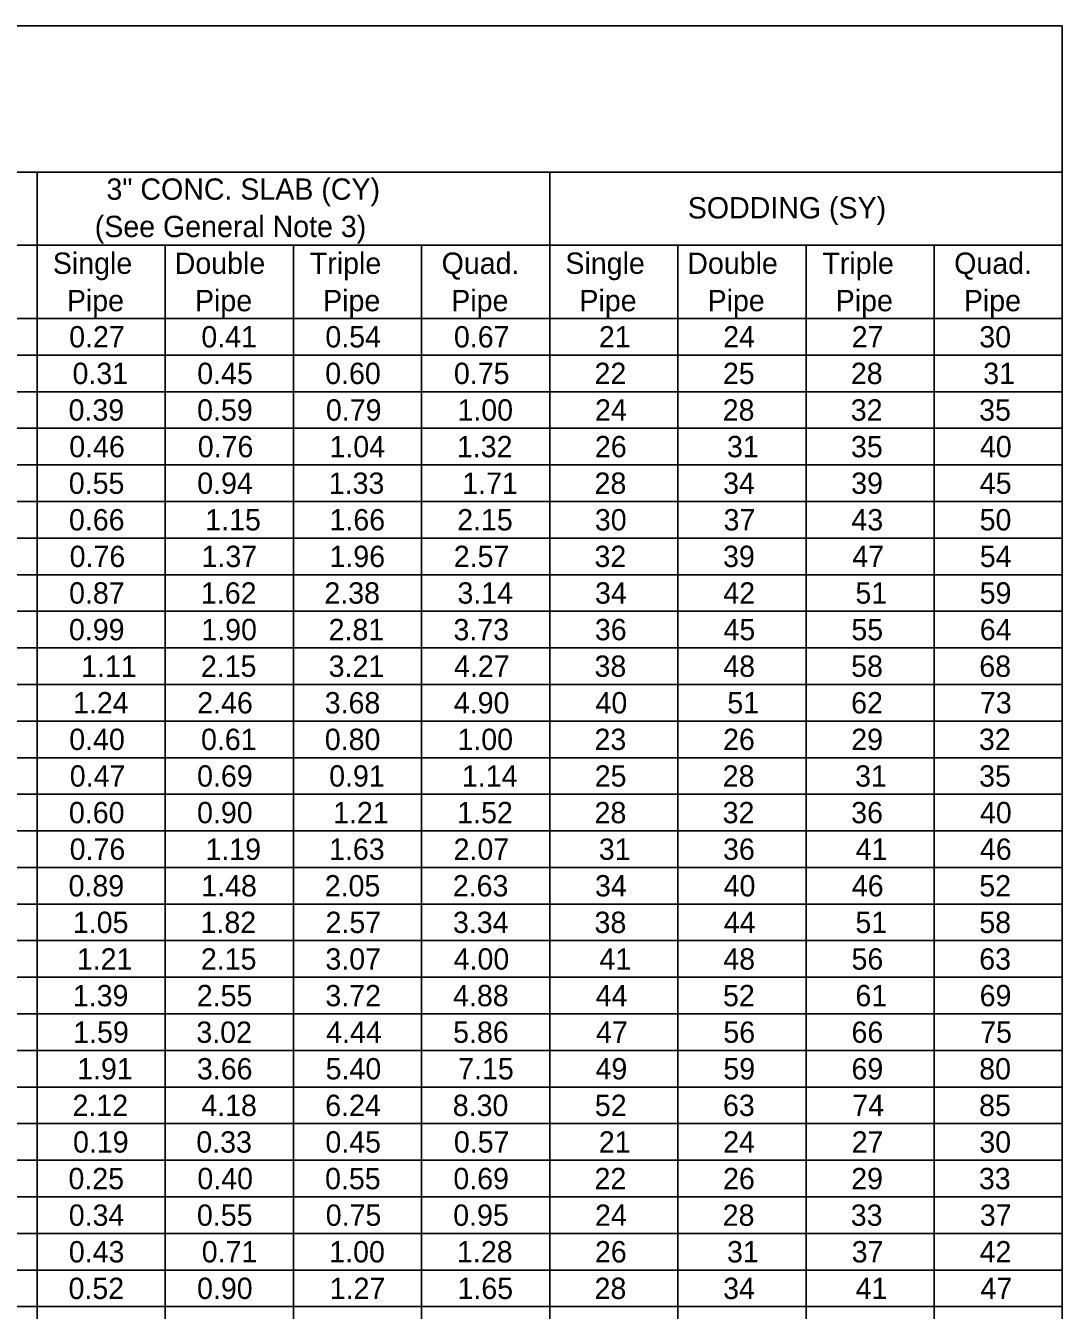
# Model space of a CAD drawing. Extents: x 1.7 to 14.6, y 0 to 8.4.
# Drawn here: x 10.062 to 13.46, y 4.218 to 8.43 of the extents above; entities that cross this region are included whole.
import ezdxf

# ---------------------------------------------------------------- set-up
doc = ezdxf.new("R2010")
doc.units = 0
doc.layers.add('Table', color=7, linetype='Continuous')

msp = doc.modelspace()

# ---------------------------------------------------------------- linework, layer by layer
at = {"layer": 'Table'}
msp.add_line((1.94, 8.43), (13.46, 8.43), dxfattribs=at)
for points in [[(13.46, 8.43), (13.46, 7.83), (13.46, 7.47), (13.46, 7.35), (13.46, 7.23), (13.46, 7.11), (13.46, 6.99), (13.46, 6.87), (13.46, 6.75), (13.46, 6.63), (13.46, 6.51), (13.46, 6.39), (13.46, 6.27), (13.46, 6.15), (13.46, 6.03), (13.46, 5.91), (13.46, 5.79), (13.46, 5.67), (13.46, 5.55), (13.46, 5.43), (13.46, 5.31), (13.46, 5.19), (13.46, 5.07), (13.46, 4.95), (13.46, 4.83), (13.46, 4.71), (13.46, 4.59), (13.46, 4.47), (13.46, 4.35), (13.46, 4.23), (13.46, 4.11)], [(13.46, 7.95), (11.78, 7.95), (10.1, 7.95), (8.42, 7.95), (8.06, 7.95), (6.38, 7.95), (6.02, 7.95), (5.66, 7.95), (5.42, 7.95), (4.94, 7.95), (4.52, 7.95), (4.04, 7.95), (3.62, 7.95), (3.2, 7.95), (2.9, 7.95), (2.6, 7.95), (2.3, 7.95), (1.94, 7.95)], [(10.1, 7.95), (10.1, 7.71), (10.1, 7.47), (10.1, 7.35), (10.1, 7.23), (10.1, 7.11), (10.1, 6.99), (10.1, 6.87), (10.1, 6.75), (10.1, 6.63), (10.1, 6.51), (10.1, 6.39), (10.1, 6.27), (10.1, 6.15), (10.1, 6.03), (10.1, 5.91), (10.1, 5.79), (10.1, 5.67), (10.1, 5.55), (10.1, 5.43), (10.1, 5.31), (10.1, 5.19), (10.1, 5.07), (10.1, 4.95), (10.1, 4.83), (10.1, 4.71), (10.1, 4.59), (10.1, 4.47), (10.1, 4.35), (10.1, 4.23), (10.1, 4.11)], [(11.78, 7.95), (11.78, 7.71), (11.78, 7.47), (11.78, 7.35), (11.78, 7.23), (11.78, 7.11), (11.78, 6.99), (11.78, 6.87), (11.78, 6.75), (11.78, 6.63), (11.78, 6.51), (11.78, 6.39), (11.78, 6.27), (11.78, 6.15), (11.78, 6.03), (11.78, 5.91), (11.78, 5.79), (11.78, 5.67), (11.78, 5.55), (11.78, 5.43), (11.78, 5.31), (11.78, 5.19), (11.78, 5.07), (11.78, 4.95), (11.78, 4.83), (11.78, 4.71), (11.78, 4.59), (11.78, 4.47), (11.78, 4.35), (11.78, 4.23), (11.78, 4.11)], [(8.42, 7.71), (8.84, 7.71), (9.26, 7.71), (9.68, 7.71), (10.1, 7.71), (10.52, 7.71), (10.94, 7.71), (11.36, 7.71), (11.78, 7.71), (12.2, 7.71), (12.62, 7.71), (13.04, 7.71), (13.46, 7.71)], [(10.52, 7.71), (10.52, 7.47), (10.52, 7.35), (10.52, 7.23), (10.52, 7.11), (10.52, 6.99), (10.52, 6.87), (10.52, 6.75), (10.52, 6.63), (10.52, 6.51), (10.52, 6.39), (10.52, 6.27), (10.52, 6.15), (10.52, 6.03), (10.52, 5.91), (10.52, 5.79), (10.52, 5.67), (10.52, 5.55), (10.52, 5.43), (10.52, 5.31), (10.52, 5.19), (10.52, 5.07), (10.52, 4.95), (10.52, 4.83), (10.52, 4.71), (10.52, 4.59), (10.52, 4.47), (10.52, 4.35), (10.52, 4.23), (10.52, 4.11)], [(10.94, 7.71), (10.94, 7.47), (10.94, 7.35), (10.94, 7.23), (10.94, 7.11), (10.94, 6.99), (10.94, 6.87), (10.94, 6.75), (10.94, 6.63), (10.94, 6.51), (10.94, 6.39), (10.94, 6.27), (10.94, 6.15), (10.94, 6.03), (10.94, 5.91), (10.94, 5.79), (10.94, 5.67), (10.94, 5.55), (10.94, 5.43), (10.94, 5.31), (10.94, 5.19), (10.94, 5.07), (10.94, 4.95), (10.94, 4.83), (10.94, 4.71), (10.94, 4.59), (10.94, 4.47), (10.94, 4.35), (10.94, 4.23), (10.94, 4.11)], [(11.36, 7.71), (11.36, 7.47), (11.36, 7.35), (11.36, 7.23), (11.36, 7.11), (11.36, 6.99), (11.36, 6.87), (11.36, 6.75), (11.36, 6.63), (11.36, 6.51), (11.36, 6.39), (11.36, 6.27), (11.36, 6.15), (11.36, 6.03), (11.36, 5.91), (11.36, 5.79), (11.36, 5.67), (11.36, 5.55), (11.36, 5.43), (11.36, 5.31), (11.36, 5.19), (11.36, 5.07), (11.36, 4.95), (11.36, 4.83), (11.36, 4.71), (11.36, 4.59), (11.36, 4.47), (11.36, 4.35), (11.36, 4.23), (11.36, 4.11)], [(12.2, 7.71), (12.2, 7.47), (12.2, 7.35), (12.2, 7.23), (12.2, 7.11), (12.2, 6.99), (12.2, 6.87), (12.2, 6.75), (12.2, 6.63), (12.2, 6.51), (12.2, 6.39), (12.2, 6.27), (12.2, 6.15), (12.2, 6.03), (12.2, 5.91), (12.2, 5.79), (12.2, 5.67), (12.2, 5.55), (12.2, 5.43), (12.2, 5.31), (12.2, 5.19), (12.2, 5.07), (12.2, 4.95), (12.2, 4.83), (12.2, 4.71), (12.2, 4.59), (12.2, 4.47), (12.2, 4.35), (12.2, 4.23), (12.2, 4.11)], [(12.62, 7.71), (12.62, 7.47), (12.62, 7.35), (12.62, 7.23), (12.62, 7.11), (12.62, 6.99), (12.62, 6.87), (12.62, 6.75), (12.62, 6.63), (12.62, 6.51), (12.62, 6.39), (12.62, 6.27), (12.62, 6.15), (12.62, 6.03), (12.62, 5.91), (12.62, 5.79), (12.62, 5.67), (12.62, 5.55), (12.62, 5.43), (12.62, 5.31), (12.62, 5.19), (12.62, 5.07), (12.62, 4.95), (12.62, 4.83), (12.62, 4.71), (12.62, 4.59), (12.62, 4.47), (12.62, 4.35), (12.62, 4.23), (12.62, 4.11)], [(13.04, 7.71), (13.04, 7.47), (13.04, 7.35), (13.04, 7.23), (13.04, 7.11), (13.04, 6.99), (13.04, 6.87), (13.04, 6.75), (13.04, 6.63), (13.04, 6.51), (13.04, 6.39), (13.04, 6.27), (13.04, 6.15), (13.04, 6.03), (13.04, 5.91), (13.04, 5.79), (13.04, 5.67), (13.04, 5.55), (13.04, 5.43), (13.04, 5.31), (13.04, 5.19), (13.04, 5.07), (13.04, 4.95), (13.04, 4.83), (13.04, 4.71), (13.04, 4.59), (13.04, 4.47), (13.04, 4.35), (13.04, 4.23), (13.04, 4.11)], [(6.02, 7.47), (6.38, 7.47), (6.8, 7.47), (7.22, 7.47), (7.64, 7.47), (8.06, 7.47), (8.42, 7.47), (8.84, 7.47), (9.26, 7.47), (9.68, 7.47), (10.1, 7.47), (10.52, 7.47), (10.94, 7.47), (11.36, 7.47), (11.78, 7.47), (12.2, 7.47), (12.62, 7.47), (13.04, 7.47), (13.46, 7.47)], [(6.02, 7.35), (6.38, 7.35), (6.8, 7.35), (7.22, 7.35), (7.64, 7.35), (8.06, 7.35), (8.42, 7.35), (8.84, 7.35), (9.26, 7.35), (9.68, 7.35), (10.1, 7.35), (10.52, 7.35), (10.94, 7.35), (11.36, 7.35), (11.78, 7.35), (12.2, 7.35), (12.62, 7.35), (13.04, 7.35), (13.46, 7.35)], [(6.02, 7.23), (6.38, 7.23), (6.8, 7.23), (7.22, 7.23), (7.64, 7.23), (8.06, 7.23), (8.42, 7.23), (8.84, 7.23), (9.26, 7.23), (9.68, 7.23), (10.1, 7.23), (10.52, 7.23), (10.94, 7.23), (11.36, 7.23), (11.78, 7.23), (12.2, 7.23), (12.62, 7.23), (13.04, 7.23), (13.46, 7.23)], [(6.02, 7.11), (6.38, 7.11), (6.8, 7.11), (7.22, 7.11), (7.64, 7.11), (8.06, 7.11), (8.42, 7.11), (8.84, 7.11), (9.26, 7.11), (9.68, 7.11), (10.1, 7.11), (10.52, 7.11), (10.94, 7.11), (11.36, 7.11), (11.78, 7.11), (12.2, 7.11), (12.62, 7.11), (13.04, 7.11), (13.46, 7.11)], [(6.02, 6.99), (6.38, 6.99), (6.8, 6.99), (7.22, 6.99), (7.64, 6.99), (8.06, 6.99), (8.42, 6.99), (8.84, 6.99), (9.26, 6.99), (9.68, 6.99), (10.1, 6.99), (10.52, 6.99), (10.94, 6.99), (11.36, 6.99), (11.78, 6.99), (12.2, 6.99), (12.62, 6.99), (13.04, 6.99), (13.46, 6.99)], [(6.02, 6.87), (6.38, 6.87), (6.8, 6.87), (7.22, 6.87), (7.64, 6.87), (8.06, 6.87), (8.42, 6.87), (8.84, 6.87), (9.26, 6.87), (9.68, 6.87), (10.1, 6.87), (10.52, 6.87), (10.94, 6.87), (11.36, 6.87), (11.78, 6.87), (12.2, 6.87), (12.62, 6.87), (13.04, 6.87), (13.46, 6.87)], [(6.02, 6.75), (6.38, 6.75), (6.8, 6.75), (7.22, 6.75), (7.64, 6.75), (8.06, 6.75), (8.42, 6.75), (8.84, 6.75), (9.26, 6.75), (9.68, 6.75), (10.1, 6.75), (10.52, 6.75), (10.94, 6.75), (11.36, 6.75), (11.78, 6.75), (12.2, 6.75), (12.62, 6.75), (13.04, 6.75), (13.46, 6.75)], [(6.02, 6.63), (6.38, 6.63), (6.8, 6.63), (7.22, 6.63), (7.64, 6.63), (8.06, 6.63), (8.42, 6.63), (8.84, 6.63), (9.26, 6.63), (9.68, 6.63), (10.1, 6.63), (10.52, 6.63), (10.94, 6.63), (11.36, 6.63), (11.78, 6.63), (12.2, 6.63), (12.62, 6.63), (13.04, 6.63), (13.46, 6.63)], [(6.02, 6.51), (6.38, 6.51), (6.8, 6.51), (7.22, 6.51), (7.64, 6.51), (8.06, 6.51), (8.42, 6.51), (8.84, 6.51), (9.26, 6.51), (9.68, 6.51), (10.1, 6.51), (10.52, 6.51), (10.94, 6.51), (11.36, 6.51), (11.78, 6.51), (12.2, 6.51), (12.62, 6.51), (13.04, 6.51), (13.46, 6.51)], [(6.02, 6.39), (6.38, 6.39), (6.8, 6.39), (7.22, 6.39), (7.64, 6.39), (8.06, 6.39), (8.42, 6.39), (8.84, 6.39), (9.26, 6.39), (9.68, 6.39), (10.1, 6.39), (10.52, 6.39), (10.94, 6.39), (11.36, 6.39), (11.78, 6.39), (12.2, 6.39), (12.62, 6.39), (13.04, 6.39), (13.46, 6.39)], [(6.02, 6.27), (6.38, 6.27), (6.8, 6.27), (7.22, 6.27), (7.64, 6.27), (8.06, 6.27), (8.42, 6.27), (8.84, 6.27), (9.26, 6.27), (9.68, 6.27), (10.1, 6.27), (10.52, 6.27), (10.94, 6.27), (11.36, 6.27), (11.78, 6.27), (12.2, 6.27), (12.62, 6.27), (13.04, 6.27), (13.46, 6.27)], [(6.02, 6.15), (6.38, 6.15), (6.8, 6.15), (7.22, 6.15), (7.64, 6.15), (8.06, 6.15), (8.42, 6.15), (8.84, 6.15), (9.26, 6.15), (9.68, 6.15), (10.1, 6.15), (10.52, 6.15), (10.94, 6.15), (11.36, 6.15), (11.78, 6.15), (12.2, 6.15), (12.62, 6.15), (13.04, 6.15), (13.46, 6.15)], [(6.02, 6.03), (6.38, 6.03), (6.8, 6.03), (7.22, 6.03), (7.64, 6.03), (8.06, 6.03), (8.42, 6.03), (8.84, 6.03), (9.26, 6.03), (9.68, 6.03), (10.1, 6.03), (10.52, 6.03), (10.94, 6.03), (11.36, 6.03), (11.78, 6.03), (12.2, 6.03), (12.62, 6.03), (13.04, 6.03), (13.46, 6.03)], [(6.02, 5.91), (6.38, 5.91), (6.8, 5.91), (7.22, 5.91), (7.64, 5.91), (8.06, 5.91), (8.42, 5.91), (8.84, 5.91), (9.26, 5.91), (9.68, 5.91), (10.1, 5.91), (10.52, 5.91), (10.94, 5.91), (11.36, 5.91), (11.78, 5.91), (12.2, 5.91), (12.62, 5.91), (13.04, 5.91), (13.46, 5.91)], [(6.02, 5.79), (6.38, 5.79), (6.8, 5.79), (7.22, 5.79), (7.64, 5.79), (8.06, 5.79), (8.42, 5.79), (8.84, 5.79), (9.26, 5.79), (9.68, 5.79), (10.1, 5.79), (10.52, 5.79), (10.94, 5.79), (11.36, 5.79), (11.78, 5.79), (12.2, 5.79), (12.62, 5.79), (13.04, 5.79), (13.46, 5.79)], [(6.02, 5.67), (6.38, 5.67), (6.8, 5.67), (7.22, 5.67), (7.64, 5.67), (8.06, 5.67), (8.42, 5.67), (8.84, 5.67), (9.26, 5.67), (9.68, 5.67), (10.1, 5.67), (10.52, 5.67), (10.94, 5.67), (11.36, 5.67), (11.78, 5.67), (12.2, 5.67), (12.62, 5.67), (13.04, 5.67), (13.46, 5.67)], [(6.02, 5.55), (6.38, 5.55), (6.8, 5.55), (7.22, 5.55), (7.64, 5.55), (8.06, 5.55), (8.42, 5.55), (8.84, 5.55), (9.26, 5.55), (9.68, 5.55), (10.1, 5.55), (10.52, 5.55), (10.94, 5.55), (11.36, 5.55), (11.78, 5.55), (12.2, 5.55), (12.62, 5.55), (13.04, 5.55), (13.46, 5.55)], [(6.02, 5.43), (6.38, 5.43), (6.8, 5.43), (7.22, 5.43), (7.64, 5.43), (8.06, 5.43), (8.42, 5.43), (8.84, 5.43), (9.26, 5.43), (9.68, 5.43), (10.1, 5.43), (10.52, 5.43), (10.94, 5.43), (11.36, 5.43), (11.78, 5.43), (12.2, 5.43), (12.62, 5.43), (13.04, 5.43), (13.46, 5.43)], [(6.02, 5.31), (6.38, 5.31), (6.8, 5.31), (7.22, 5.31), (7.64, 5.31), (8.06, 5.31), (8.42, 5.31), (8.84, 5.31), (9.26, 5.31), (9.68, 5.31), (10.1, 5.31), (10.52, 5.31), (10.94, 5.31), (11.36, 5.31), (11.78, 5.31), (12.2, 5.31), (12.62, 5.31), (13.04, 5.31), (13.46, 5.31)], [(6.02, 5.19), (6.38, 5.19), (6.8, 5.19), (7.22, 5.19), (7.64, 5.19), (8.06, 5.19), (8.42, 5.19), (8.84, 5.19), (9.26, 5.19), (9.68, 5.19), (10.1, 5.19), (10.52, 5.19), (10.94, 5.19), (11.36, 5.19), (11.78, 5.19), (12.2, 5.19), (12.62, 5.19), (13.04, 5.19), (13.46, 5.19)], [(6.02, 5.07), (6.38, 5.07), (6.8, 5.07), (7.22, 5.07), (7.64, 5.07), (8.06, 5.07), (8.42, 5.07), (8.84, 5.07), (9.26, 5.07), (9.68, 5.07), (10.1, 5.07), (10.52, 5.07), (10.94, 5.07), (11.36, 5.07), (11.78, 5.07), (12.2, 5.07), (12.62, 5.07), (13.04, 5.07), (13.46, 5.07)], [(6.02, 4.95), (6.38, 4.95), (6.8, 4.95), (7.22, 4.95), (7.64, 4.95), (8.06, 4.95), (8.42, 4.95), (8.84, 4.95), (9.26, 4.95), (9.68, 4.95), (10.1, 4.95), (10.52, 4.95), (10.94, 4.95), (11.36, 4.95), (11.78, 4.95), (12.2, 4.95), (12.62, 4.95), (13.04, 4.95), (13.46, 4.95)], [(6.02, 4.83), (6.38, 4.83), (6.8, 4.83), (7.22, 4.83), (7.64, 4.83), (8.06, 4.83), (8.42, 4.83), (8.84, 4.83), (9.26, 4.83), (9.68, 4.83), (10.1, 4.83), (10.52, 4.83), (10.94, 4.83), (11.36, 4.83), (11.78, 4.83), (12.2, 4.83), (12.62, 4.83), (13.04, 4.83), (13.46, 4.83)], [(6.02, 4.71), (6.38, 4.71), (6.8, 4.71), (7.22, 4.71), (7.64, 4.71), (8.06, 4.71), (8.42, 4.71), (8.84, 4.71), (9.26, 4.71), (9.68, 4.71), (10.1, 4.71), (10.52, 4.71), (10.94, 4.71), (11.36, 4.71), (11.78, 4.71), (12.2, 4.71), (12.62, 4.71), (13.04, 4.71), (13.46, 4.71)], [(6.02, 4.59), (6.38, 4.59), (6.8, 4.59), (7.22, 4.59), (7.64, 4.59), (8.06, 4.59), (8.42, 4.59), (8.84, 4.59), (9.26, 4.59), (9.68, 4.59), (10.1, 4.59), (10.52, 4.59), (10.94, 4.59), (11.36, 4.59), (11.78, 4.59), (12.2, 4.59), (12.62, 4.59), (13.04, 4.59), (13.46, 4.59)], [(6.02, 4.47), (6.38, 4.47), (6.8, 4.47), (7.22, 4.47), (7.64, 4.47), (8.06, 4.47), (8.42, 4.47), (8.84, 4.47), (9.26, 4.47), (9.68, 4.47), (10.1, 4.47), (10.52, 4.47), (10.94, 4.47), (11.36, 4.47), (11.78, 4.47), (12.2, 4.47), (12.62, 4.47), (13.04, 4.47), (13.46, 4.47)], [(6.02, 4.35), (6.38, 4.35), (6.8, 4.35), (7.22, 4.35), (7.64, 4.35), (8.06, 4.35), (8.42, 4.35), (8.84, 4.35), (9.26, 4.35), (9.68, 4.35), (10.1, 4.35), (10.52, 4.35), (10.94, 4.35), (11.36, 4.35), (11.78, 4.35), (12.2, 4.35), (12.62, 4.35), (13.04, 4.35), (13.46, 4.35)], [(6.02, 4.23), (6.38, 4.23), (6.8, 4.23), (7.22, 4.23), (7.64, 4.23), (8.06, 4.23), (8.42, 4.23), (8.84, 4.23), (9.26, 4.23), (9.68, 4.23), (10.1, 4.23), (10.52, 4.23), (10.94, 4.23), (11.36, 4.23), (11.78, 4.23), (12.2, 4.23), (12.62, 4.23), (13.04, 4.23), (13.46, 4.23)]]:
    msp.add_lwpolyline(points, dxfattribs=at)

# ---------------------------------------------------------------- texts
for s, p in [('3" CONC. SLAB (CY)', (10.3271, 7.8592)), ('SODDING (SY)', (12.2325, 7.7979)), ('(See General Note 3)', (10.2888, 7.7367)), ('Single', (10.1514, 7.6162)), ('Double', (10.5509, 7.6162)), ('Triple', (10.9937, 7.6162)), ('Quad.', (11.4257, 7.6162)), ('Single', (11.8314, 7.6162)), ('Double', (12.2309, 7.6162)), ('Triple', (12.6737, 7.6162)), ('Quad.', (13.1057, 7.6162)), ('Pipe', (10.1973, 7.4937)), ('Pipe', (10.6173, 7.4937)), ('Pipe', (11.0373, 7.4937)), ('Pipe', (11.4573, 7.4937)), ('Pipe', (11.8773, 7.4937)), ('Pipe', (12.2973, 7.4937)), ('Pipe', (12.7173, 7.4937)), ('Pipe', (13.1373, 7.4937)), ('0.27', (10.2049, 7.375)), ('0.41', (10.6381, 7.375)), ('0.54', (11.0446, 7.375)), ('0.67', (11.466, 7.375)), ('0.31', (10.2159, 7.255)), ('0.45', (10.6247, 7.255)), ('0.60', (11.0441, 7.255)), ('0.75', (11.4659, 7.255)), ('0.39', (10.203, 7.135)), ('0.59', (10.6242, 7.135)), ('0.79', (11.0465, 7.135)), ('1.00', (11.4775, 7.135)), ('0.46', (10.2052, 7.015)), ('0.76', (10.6265, 7.015)), ('1.04', (11.0581, 7.015)), ('1.32', (11.4758, 7.015)), ('0.55', (10.2037, 6.895)), ('0.94', (10.6247, 6.895)), ('1.33', (11.0557, 6.895)), ('1.71', (11.4933, 6.895)), ('0.66', (10.2042, 6.775)), ('1.15', (10.6511, 6.775)), ('1.66', (11.0582, 6.775)), ('2.15', (11.4766, 6.775)), ('0.76', (10.2065, 6.655)), ('1.37', (10.6388, 6.655)), ('1.96', (11.0582, 6.655)), ('2.57', (11.4654, 6.655)), ('0.87', (10.2046, 6.535)), ('1.62', (10.6369, 6.535)), ('2.38', (11.0414, 6.535)), ('3.14', (11.4775, 6.535)), ('0.99', (10.2042, 6.415)), ('1.90', (10.6381, 6.415)), ('2.81', (11.0553, 6.415)), ('3.73', (11.4645, 6.415)), ('1.11', (10.2445, 6.295)), ('2.15', (10.6366, 6.295)), ('3.21', (11.0554, 6.295)), ('4.27', (11.4664, 6.295)), ('1.24', (10.2176, 6.175)), ('2.46', (10.6247, 6.175)), ('3.68', (11.0425, 6.175)), ('4.90', (11.4657, 6.175)), ('0.40', (10.2051, 6.055)), ('0.61', (10.6371, 6.055)), ('0.80', (11.0428, 6.055)), ('1.00', (11.4775, 6.055)), ('0.47', (10.2069, 5.935)), ('0.69', (10.6242, 5.935)), ('0.91', (11.0571, 5.935)), ('1.14', (11.4921, 5.935)), ('0.60', (10.2041, 5.815)), ('0.90', (10.6241, 5.815)), ('1.21', (11.07, 5.815)), ('1.52', (11.4769, 5.815)), ('0.76', (10.2065, 5.695)), ('1.19', (10.6516, 5.695)), ('1.63', (11.0568, 5.695)), ('2.07', (11.4649, 5.695)), ('0.89', (10.2029, 5.575)), ('1.48', (10.638, 5.575)), ('2.05', (11.0426, 5.575)), ('2.63', (11.4623, 5.575)), ('1.05', (10.2171, 5.455)), ('1.82', (10.6356, 5.455)), ('2.57', (11.0454, 5.455)), ('3.34', (11.4629, 5.455)), ('1.21', (10.23, 5.335)), ('2.15', (10.6366, 5.335)), ('3.07', (11.0448, 5.335)), ('4.00', (11.4651, 5.335)), ('1.39', (10.217, 5.215)), ('2.55', (10.6231, 5.215)), ('3.72', (11.0446, 5.215)), ('4.88', (11.4633, 5.215)), ('1.59', (10.2182, 5.095)), ('3.02', (10.6218, 5.095)), ('4.44', (11.0472, 5.095)), ('5.86', (11.4634, 5.095)), ('1.91', (10.2311, 4.975)), ('3.66', (10.6236, 4.975)), ('5.40', (11.0456, 4.975)), ('7.15', (11.4799, 4.975)), ('2.12', (10.2158, 4.855)), ('4.18', (10.638, 4.855)), ('6.24', (11.0442, 4.855)), ('8.30', (11.4622, 4.855)), ('0.19', (10.2176, 4.735)), ('0.33', (10.6217, 4.735)), ('0.45', (11.0447, 4.735)), ('0.57', (11.4659, 4.735)), ('0.25', (10.2026, 4.615)), ('0.40', (10.6251, 4.615)), ('0.55', (11.0437, 4.615)), ('0.69', (11.4642, 4.615)), ('0.34', (10.2035, 4.495)), ('0.55', (10.6237, 4.495)), ('0.75', (11.0459, 4.495)), ('0.95', (11.4637, 4.495)), ('0.43', (10.2038, 4.375)), ('0.71', (10.6394, 4.375)), ('1.00', (11.0575, 4.375)), ('1.28', (11.476, 4.375)), ('0.52', (10.2029, 4.255)), ('0.90', (10.6241, 4.255)), ('1.27', (11.0589, 4.255)), ('1.65', (11.4777, 4.255))]:
    msp.add_text(s, height=0.07, dxfattribs=at).set_placement(p)
for s, p in [('21', (11.941, 7.375)), ('24', (12.3485, 7.375)), ('27', (12.7698, 7.375)), ('30', (13.1879, 7.375)), ('22', (11.9268, 7.255)), ('25', (12.3475, 7.255)), ('28', (12.7669, 7.255)), ('31', (13.2009, 7.255)), ('24', (11.9285, 7.135)), ('28', (12.3469, 7.135)), ('32', (12.7667, 7.135)), ('35', (13.1874, 7.135)), ('26', (11.9281, 7.015)), ('31', (12.3609, 7.015)), ('35', (12.7674, 7.015)), ('40', (13.19, 7.015)), ('28', (11.9269, 6.895)), ('34', (12.3484, 6.895)), ('39', (12.768, 6.895)), ('45', (13.1896, 6.895)), ('30', (11.9279, 6.775)), ('37', (12.3497, 6.775)), ('43', (12.7688, 6.775)), ('50', (13.189, 6.775)), ('32', (11.9267, 6.655)), ('39', (12.348, 6.655)), ('47', (12.7719, 6.655)), ('54', (13.1896, 6.655)), ('34', (11.9284, 6.535)), ('42', (12.3489, 6.535)), ('51', (12.782, 6.535)), ('59', (13.1891, 6.535)), ('36', (11.928, 6.415)), ('45', (12.3496, 6.415)), ('55', (12.7686, 6.415)), ('64', (13.1896, 6.415)), ('38', (11.9268, 6.295)), ('48', (12.349, 6.295)), ('58', (12.768, 6.295)), ('68', (13.188, 6.295)), ('40', (11.93, 6.175)), ('51', (12.362, 6.175)), ('62', (12.7679, 6.175)), ('73', (13.19, 6.175)), ('23', (11.9267, 6.055)), ('26', (12.3481, 6.055)), ('29', (12.7681, 6.055)), ('32', (13.1867, 6.055)), ('25', (11.9275, 5.935)), ('28', (12.3469, 5.935)), ('31', (12.7809, 5.935)), ('35', (13.1874, 5.935)), ('28', (11.9269, 5.815)), ('32', (12.3467, 5.815)), ('36', (12.768, 5.815)), ('40', (13.19, 5.815)), ('31', (11.9409, 5.695)), ('36', (12.348, 5.695)), ('41', (12.783, 5.695)), ('46', (13.1901, 5.695)), ('34', (11.9284, 5.575)), ('40', (12.35, 5.575)), ('46', (12.7701, 5.575)), ('52', (13.1879, 5.575)), ('38', (11.9268, 5.455)), ('44', (12.3506, 5.455)), ('51', (12.782, 5.455)), ('58', (13.188, 5.455)), ('41', (11.943, 5.335)), ('48', (12.349, 5.335)), ('56', (12.7691, 5.335)), ('63', (13.1878, 5.335)), ('44', (11.9306, 5.215)), ('52', (12.3479, 5.215)), ('61', (12.782, 5.215)), ('69', (13.1891, 5.215)), ('47', (11.9319, 5.095)), ('56', (12.3491, 5.095)), ('66', (12.7691, 5.095)), ('75', (13.1909, 5.095)), ('49', (11.9301, 4.975)), ('59', (12.3491, 4.975)), ('69', (12.7691, 4.975)), ('80', (13.1877, 4.975)), ('52', (11.9279, 4.855)), ('63', (12.3478, 4.855)), ('74', (12.7719, 4.855)), ('85', (13.1873, 4.855)), ('21', (11.941, 4.735)), ('24', (12.3485, 4.735)), ('27', (12.7698, 4.735)), ('30', (13.1879, 4.735)), ('22', (11.9268, 4.615)), ('26', (12.3481, 4.615)), ('29', (12.7681, 4.615)), ('33', (13.1866, 4.615)), ('24', (11.9285, 4.495)), ('28', (12.3469, 4.495)), ('33', (12.7666, 4.495)), ('37', (13.1897, 4.495)), ('26', (11.9281, 4.375)), ('31', (12.3609, 4.375)), ('37', (12.7697, 4.375)), ('42', (13.1889, 4.375)), ('28', (11.9269, 4.255)), ('34', (12.3484, 4.255)), ('41', (12.783, 4.255)), ('47', (13.1919, 4.255))]:
    msp.add_text(s, height=0.07, rotation=0, dxfattribs=at).set_placement(p)

doc.saveas('drawing.dxf')
